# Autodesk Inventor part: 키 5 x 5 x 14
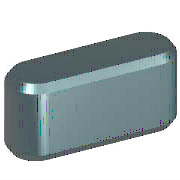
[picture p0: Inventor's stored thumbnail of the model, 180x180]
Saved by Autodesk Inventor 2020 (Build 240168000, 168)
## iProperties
IsCustomPart: 1
Created: 2012-02
Part Number: 키 5 x 5 x 14
Material: 강철, 연강
Description: 키 및 해당 키홈
Document SubType Name: Modeling
Standard: KS B 1311
Designer: mduedu
Standards Organization: KS
Language: ko-KR
Size Designation: 4 x 4 x 12
Categories: <MemberInstance><Categories><Category DisplayName="샤프트 부품" InternalName="7f7aeb1f-a693-4053-b835-cee3144e0d98" Mnemonic="SHFT"><Category DisplayName="키" Interna
Density: 1 g/cm^3
Appearance: 노란색
Author: mduedu
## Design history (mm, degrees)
workplane "Work Plane1"
workplane "Work Plane2"
sketch "스케치1"
  geometry: L1 (2.5, 2.5)-(11.5, 2.5); L2 (11.5, -2.5)-(2.5, -2.5); L3 (0, 8.9)-(0, -4.4) reference; L4 (-2.8, 0)-(16.8, 0) reference; L5 (14, 0)-(14, 7); A1 r 2.5 centre (2.5, 0) between (2.5, 2.5) and (2.5, -2.5); A2 r 2.5 centre (11.5, 0) between (11.5, -2.5) and (11.5, 2.5)
  constraints: 6 end point, 5 point on circle, 4 tangent, 3 point on line, 2 centre point, 1 horizontal, 1 parallel, 1 perpendicular
  dimensions: "d0" = 2.5 radius of A1 (= 0.5 x PB); "d13" = 2.5 radius of A2 (= 0.5 x PB); "d14" = 14 distance between parallel lines of L5 L3 (= NLG)
extrude "본체1" new body sketch "스케치1" taper "d3" = 0 deg; stored distance "d4" = 10
workplane "Work Plane3"
body "Solid1"
chamfer "모따기1" distance "d8" = 0.25 (= PHH); stored, may be unused: second distance "d9" = 0.25 (= PHH), angle "d15" = 45 deg
other parameters: "d1" = -3 (= -PNT), "d2" = 2 (= PH - PNT), "NLG" = 14 [user parameter; used in 3 equation terms], "PB" = 5 [user parameter; used in 2 equation terms], "PNT" = 3 [user parameter; used in 2 equation terms], "PH" = 5 [user parameter; used in 1 equation term], "PHH" = 0.25 [user parameter; used in 2 equation terms], "d10" = 0, "d16" = 0, "d17" = 0, "d18" = 0, "PLB2" = 14 (= NLG) [user parameter], "WDMAX" = 12 [user parameter], "PLB1" = 14 (= NLG) [user parameter], "RR" = 0.08 [user parameter], "PUEB" = 1.8 [user parameter]
